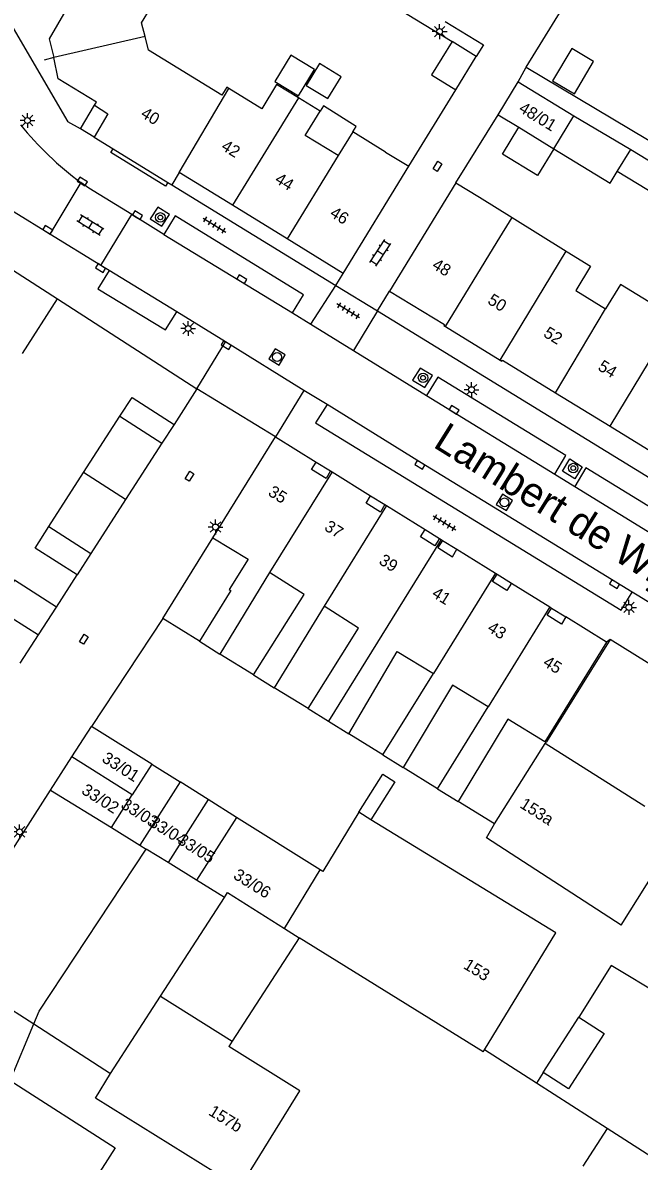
# Model space of a CAD drawing. Extents: x 132998 to 136004, y 396998 to 398512.
# Drawn here: x 133425.6 to 133477.5, y 397867.7 to 397963.6 of the extents above; entities that cross this region are included whole.
import ezdxf

# ---------------------------------------------------------------- set-up
doc = ezdxf.new("R2010")
doc.units = 0
for name, color, linetype in [('gg-afsc-erfafscheiding', 7, 'Continuous'), ('gg-afsc-hekwerk', 7, 'Continuous'), ('gg-afsc-muur', 7, 'Continuous'), ('gg-anno-huisnummerreeks BGT', 7, 'Continuous'), ('gg-anno-openbare ruimte label', 7, 'Continuous'), ('gg-bbg-bijgebouw', 7, 'Continuous'), ('gg-bbg-gedigitaliseerde bebouwing', 7, 'Continuous'), ('gg-bbg-gedigitaliseerde bijgebouw', 7, 'Continuous'), ('gg-bbg-hoofdgebouw', 7, 'Continuous'), ('gg-bbg-luifel en loopbrug', 7, 'Continuous'), ('gg-bbg-onder overbouw', 7, 'Continuous'), ('gg-bbg-pand overbouw', 7, 'Continuous'), ('gg-bbg-tussenscheiding', 7, 'Continuous'), ('gg-knt-verharding', 7, 'Continuous'), ('gg-knt-verharding nz', 7, 'Continuous'), ('gt-grn-vlakafsluiter', 7, 'Continuous'), ('gt-grn-weggrens', 7, 'Continuous'), ('gt-symb-boom', 7, 'Continuous'), ('gt-symb-klinker verharding', 7, 'Continuous'), ('gt-symb-kolk', 7, 'Continuous'), ('gt-symb-kolk center center', 7, 'Continuous'), ('gt-symb-lichtmast', 7, 'Continuous'), ('gt-symb-rioolschacht', 7, 'Continuous'), ('gt-symb-tegel verharding', 7, 'Continuous')]:
    doc.layers.add(name, color=color, linetype=linetype)

# ---------------------------------------------------------------- blocks, each defined once
blk = doc.blocks.new('gt0-BOOM')
at = {"layer": 'gt-symb-boom'}
for radius in [0.4, 0.2]:
    blk.add_circle((0, 0), radius, dxfattribs=at)
blk = doc.blocks.new('gt0-LMAST')
at = {"layer": 'gt-symb-lichtmast'}
for p, q in [((-0.182, 0.173), (-0.447, 0.438)), ((-0.005, 0.246), (-0.005, 0.621)), ((0.172, 0.173), (0.437, 0.438)), ((-0.255, -0.004), (-0.63, -0.004)), ((-0.182, -0.181), (-0.447, -0.446)), ((-0.005, -0.254), (-0.005, -0.629)), ((0.437, -0.446), (0.172, -0.181)), ((0.245, -0.004), (0.62, -0.004))]:
    blk.add_line(p, q, dxfattribs=at)
blk.add_circle((-0.005, -0.004), 0.25, dxfattribs=at)
blk = doc.blocks.new('gt0-KOLK')
at = {"layer": 'gt-symb-kolk'}
blk.add_lwpolyline([(0, 0), (0.375, 0), (0.375, 0.4), (-0.375, 0.4), (-0.375, 0), (0, 0)], dxfattribs=at)
blk = doc.blocks.new('gt0-KL1')
at = {"layer": 'gt-symb-klinker verharding'}
for p, q in [((-1.15, 0.3), (1.15, 0.3)), ((-1, -0.3), (-1, 0.3)), ((-0.5, 0.3), (-0.5, 0.45)), ((0, -0.3), (0, 0.3)), ((0.5, 0.3), (0.5, 0.45)), ((1, -0.3), (1, 0.3)), ((-1.15, -0.3), (1.15, -0.3)), ((-0.5, -0.45), (-0.5, -0.3)), ((0.5, -0.45), (0.5, -0.3))]:
    blk.add_line(p, q, dxfattribs=at)
blk = doc.blocks.new('gt0-KOLKCC')
at = {"layer": 'gt-symb-kolk center center'}
blk.add_lwpolyline([(-0.375, 0.2), (0.375, 0.2), (0.375, -0.2), (-0.375, -0.2)], close=True, dxfattribs=at)
blk = doc.blocks.new('gt0-TEG1')
at = {"layer": 'gt-symb-tegel verharding'}
for p, q in [((-1.125, 0), (1.125, 0)), ((-0.9, -0.25), (-0.9, 0.25)), ((-0.45, -0.25), (-0.45, 0.25)), ((0, -0.25), (0, 0.25)), ((0.45, -0.25), (0.45, 0.25)), ((0.9, -0.25), (0.9, 0.25))]:
    blk.add_line(p, q, dxfattribs=at)
blk = doc.blocks.new('gt0-RS')
at = {"layer": 'gt-symb-rioolschacht'}
blk.add_lwpolyline([(-0.5, -0.5), (0.5, -0.5), (0.5, 0.5), (-0.5, 0.5)], close=True, dxfattribs=at)
blk.add_circle((0, 0), 0.375, dxfattribs=at)

msp = doc.modelspace()

# ---------------------------------------------------------------- linework, layer by layer
at = {"layer": 'gg-afsc-erfafscheiding'}
for p, q in [((133467.987, 397959.829), (133500.702, 397940.273)), ((133428.55, 397940.32), (133440.28, 397932.74)), ((133440.28, 397932.74), (133438.36, 397929.75)), ((133440.488, 397911.502), (133437.42, 397913.411)), ((133445.051, 397908.68), (133442.219, 397910.419)), ((133449.642, 397905.845), (133446.781, 397907.593)), ((133455.916, 397901.956), (133453.07, 397903.712)), ((133460.544, 397899.077), (133457.653, 397900.884)), ((133465.32, 397896.147), (133462.284, 397898.01)), ((133469.426, 397875.2), (133468.863, 397874.313))]:
    msp.add_line(p, q, dxfattribs=at)
for points in [[(133452.519, 397966.43), (133452.815, 397965.486), (133453.519, 397964.851), (133455.624, 397965.741), (133461.761, 397961.967)], [(133461.167, 397963.674), (133464.396, 397961.689), (133463.797, 397960.715)], [(133483.745, 397879.058), (133475.138, 397884.2), (133472.427, 397879.856)]]:
    msp.add_lwpolyline(points, dxfattribs=at)
at = {"layer": 'gg-afsc-hekwerk'}
msp.add_line((133437.42, 397913.411), (133431.4, 397904.34), dxfattribs=at)
at = {"layer": 'gg-afsc-muur'}
for p, q in [((133467.987, 397959.829), (133474.941, 397971.075)), ((133428.249, 397960.622), (133427.42, 397960.42)), ((133458.121, 397951.479), (133462.073, 397957.913)), ((133462.083, 397950.072), (133465.643, 397955.82)), ((133437.42, 397913.411), (133441.63, 397920.204)), ((133468.863, 397874.313), (133464.486, 397877.129)), ((133474.802, 397870.492), (133468.863, 397874.313))]:
    msp.add_line(p, q, dxfattribs=at)
at = {"layer": 'gg-bbg-bijgebouw'}
for p, q in [((133463.797, 397960.715), (133461.761, 397961.967)), ((133462.073, 397957.913), (133463.797, 397960.715)), ((133465.643, 397955.82), (133467.331, 397958.581)), ((133467.331, 397958.581), (133472.01, 397955.72)), ((133430.74, 397925.7), (133433.802, 397930.439)), ((133438.36, 397929.75), (133437.337, 397928.167)), ((133437.337, 397928.167), (133434.27, 397923.42)), ((133431.35, 397918.88), (133430.2, 397917.08)), ((133443.123, 397915.772), (133440.488, 397911.502)), ((133425.414, 397909.658), (133426.953, 397912.043)), ((133440.488, 397911.502), (133442.219, 397910.419)), ((133479.219, 397909.058), (133475.06, 397911.65)), ((133445.051, 397908.68), (133446.781, 397907.593)), ((133449.642, 397905.845), (133451.356, 397904.779)), ((133429.759, 397901.779), (133431.4, 397904.34)), ((133436.477, 397901.157), (133431.4, 397904.34)), ((133451.356, 397904.779), (133453.07, 397903.712)), ((133427.964, 397898.977), (133429.759, 397901.779)), ((133455.916, 397901.956), (133457.653, 397900.884)), ((133436.477, 397901.157), (133438.859, 397899.665)), ((133441.24, 397898.171), (133438.859, 397899.665)), ((133418.624, 397884.4), (133427.964, 397898.977)), ((133460.544, 397899.077), (133462.284, 397898.01)), ((133443.621, 397896.679), (133441.24, 397898.171)), ((133450.653, 397892.271), (133443.621, 397896.679)), ((133469.426, 397875.2), (133472.427, 397879.856))]:
    msp.add_line(p, q, dxfattribs=at)
for points in [[(133433.802, 397930.439), (133434.83, 397932.03), (133438.36, 397929.75)], [(133430.2, 397917.08), (133426.66, 397919.35), (133427.815, 397921.151)]]:
    msp.add_lwpolyline(points, dxfattribs=at)
at = {"layer": 'gg-bbg-gedigitaliseerde bebouwing'}
for p, q in [((133450.65, 397956.124), (133448.833, 397957.236)), ((133453.391, 397954.373), (133452.171, 397952.379)), ((133456.161, 397952.678), (133453.391, 397954.373)), ((133456.161, 397952.678), (133458.121, 397951.479)), ((133462.083, 397950.072), (133464.059, 397948.876)), ((133464.059, 397948.876), (133466.805, 397947.165)), ((133466.805, 397947.165), (133471.356, 397944.328)), ((133471.356, 397944.328), (133471.438, 397944.277)), ((133425.595, 397935.713), (133428.55, 397940.32)), ((133446.38, 397917.288), (133442.219, 397910.419)), ((133451, 397914.451), (133446.781, 397907.593)), ((133455.916, 397901.956), (133460.204, 397908.799)), ((133460.544, 397899.077), (133464.79, 397905.984)), ((133466.438, 397904.957), (133462.284, 397898.01)), ((133465.32, 397896.147), (133469.598, 397902.889)), ((133476, 397887.596), (133479.483, 397893.191)), ((133464.382, 397876.959), (133448.881, 397886.549)), ((133474.802, 397870.492), (133472.776, 397867.333))]:
    msp.add_line(p, q, dxfattribs=at)
for points in [[(133435.924, 397962.401), (133435.629, 397963.564), (133439.403, 397969.757), (133440.113, 397969.324), (133440.217, 397969.495)], [(133442.966, 397958.029), (133442.79, 397958.138), (133442.365, 397957.449), (133436.217, 397961.242), (133435.924, 397962.401)], [(133448.833, 397957.236), (133446.991, 397958.364), (133445.732, 397956.323), (133442.966, 397958.029)], [(133452.171, 397952.379), (133449.397, 397954.077), (133450.65, 397956.124)], [(133471.438, 397944.277), (133473.42, 397943.063), (133472.169, 397941.021), (133474.684, 397939.48)], [(133480.551, 397938.694), (133475.939, 397941.523), (133474.684, 397939.48)], [(133445.051, 397908.68), (133449.31, 397915.446), (133446.38, 397917.288)], [(133449.642, 397905.845), (133453.895, 397912.616), (133451, 397914.451)], [(133474.768, 397911.424), (133469.569, 397903.049), (133466.438, 397904.957)], [(133453.07, 397903.712), (133457.131, 397910.628), (133460.204, 397908.799)], [(133464.79, 397905.984), (133461.788, 397907.798), (133457.653, 397900.884)]]:
    msp.add_lwpolyline(points, dxfattribs=at)
at = {"layer": 'gg-bbg-gedigitaliseerde bijgebouw'}
for p, q in [((133465.643, 397955.82), (133467.374, 397954.762)), ((133470.326, 397952.958), (133472.01, 397955.72)), ((133467.374, 397954.762), (133470.326, 397952.958)), ((133475.661, 397951.026), (133476.799, 397952.876)), ((133476.799, 397952.876), (133480.205, 397950.804)), ((133479.065, 397948.955), (133475.661, 397951.026)), ((133427.815, 397921.151), (133430.74, 397925.7)), ((133434.27, 397923.42), (133431.35, 397918.88)), ((133423.399, 397914.283), (133426.953, 397912.043)), ((133475.06, 397911.65), (133469.693, 397903.041)), ((133469.598, 397902.889), (133469.693, 397903.041)), ((133448.881, 397886.549), (133443.249, 397877.834)), ((133424.566, 397874.537), (133426.547, 397879.306)), ((133426.547, 397879.306), (133433.017, 397875.125)), ((133443.249, 397877.834), (133442.959, 397877.385))]:
    msp.add_line(p, q, dxfattribs=at)
for points in [[(133461.761, 397961.967), (133460.038, 397959.165), (133462.073, 397957.913)], [(133446.843, 397958.623), (133448.823, 397957.411), (133450.175, 397959.61), (133448.196, 397960.826), (133446.843, 397958.623)], [(133470.217, 397958.673), (133472.05, 397957.576), (133473.671, 397960.287), (133471.837, 397961.383), (133470.217, 397958.673)], [(133452.419, 397959.002), (133450.604, 397960.117), (133449.479, 397958.286), (133451.293, 397957.171), (133452.419, 397959.002)], [(133472.427, 397879.856), (133474.551, 397878.487), (133471.55, 397873.831), (133469.426, 397875.2)], [(133443.88, 397865.51), (133448.946, 397873.664), (133442.959, 397877.385)], [(133424.566, 397874.537), (133433.414, 397868.868), (133430.126, 397863.737)], [(133441.841, 397866.777), (133431.733, 397873.058), (133433.017, 397875.125)]]:
    msp.add_lwpolyline(points, dxfattribs=at)
at = {"layer": 'gg-bbg-hoofdgebouw'}
for p, q in [((133431.623, 397953.934), (133433.242, 397952.941)), ((133433.242, 397952.941), (133437.838, 397950.124)), ((133452.595, 397942.463), (133458.121, 397951.479)), ((133438.8, 397950.94), (133438.17, 397949.92)), ((133443.274, 397948.191), (133438.8, 397950.94)), ((133437.838, 397950.124), (133438.17, 397949.92)), ((133462.083, 397950.072), (133456.486, 397940.96)), ((133447.883, 397945.358), (133443.274, 397948.191)), ((133420.51, 397945.49), (133428.55, 397940.32)), ((133452.595, 397942.463), (133447.883, 397945.358)), ((133461.209, 397937.999), (133465.801, 397935.158)), ((133470.47, 397932.42), (133475.072, 397929.595)), ((133475.072, 397929.595), (133479.674, 397926.769)), ((133441.63, 397920.204), (133446.904, 397928.7)), ((133446.904, 397928.7), (133450.309, 397926.57)), ((133451.527, 397925.857), (133451.664, 397925.771)), ((133451.664, 397925.771), (133454.898, 397923.731)), ((133456.106, 397923), (133456.237, 397922.918)), ((133456.237, 397922.918), (133459.483, 397920.904)), ((133460.693, 397920.155), (133460.826, 397920.07)), ((133460.826, 397920.07), (133460.945, 397919.994)), ((133462.166, 397919.242), (133465.415, 397917.22)), ((133465.415, 397917.22), (133465.547, 397917.138)), ((133466.765, 397916.386), (133469.988, 397914.386)), ((133469.988, 397914.386), (133470.131, 397914.297)), ((133474.768, 397911.424), (133471.345, 397913.548)), ((133454.916, 397896.486), (133453.902, 397897.107)), ((133470.483, 397886.958), (133454.916, 397896.486)), ((133464.653, 397894.957), (133465.32, 397896.147)), ((133476, 397887.596), (133464.653, 397894.957)), ((133464.486, 397877.129), (133470.483, 397886.958)), ((133464.382, 397876.959), (133464.486, 397877.129)), ((133485.6, 397863.57), (133474.802, 397870.492))]:
    msp.add_line(p, q, dxfattribs=at)
for points in [[(133429.495, 397965.68), (133429.765, 397965.509), (133427.832, 397962.201), (133428.249, 397960.622)], [(133431.673, 397956.607), (133431.836, 397956.871), (133428.614, 397958.844), (133428.249, 397960.622)], [(133456.486, 397940.96), (133461.119, 397938.173), (133461.066, 397938.088), (133461.209, 397937.999)], [(133465.801, 397935.158), (133465.938, 397935.073), (133465.996, 397935.167), (133470.47, 397932.42)], [(133441.63, 397920.204), (133444.586, 397918.402), (133443.003, 397915.849), (133443.123, 397915.772)], [(133453.902, 397897.107), (133450.873, 397892.133), (133450.653, 397892.271)]]:
    msp.add_lwpolyline(points, dxfattribs=at)
at = {"layer": 'gg-bbg-luifel en loopbrug'}
for p, q in [((133472.01, 397955.72), (133476.799, 397952.876)), ((133426.953, 397912.043), (133428.451, 397914.363))]:
    msp.add_line(p, q, dxfattribs=at)
for points in [[(133453.391, 397954.373), (133453.673, 397954.815), (133450.932, 397956.566), (133450.65, 397956.124)], [(133470.326, 397952.958), (133468.95, 397950.7), (133465.998, 397952.503), (133467.374, 397954.762)], [(133470.326, 397952.958), (133475.067, 397950.06), (133475.661, 397951.026)], [(133428.451, 397914.363), (133424.92, 397916.635), (133423.399, 397914.283)], [(133453.902, 397897.107), (133455.923, 397900.315), (133456.929, 397899.681), (133454.916, 397896.486)]]:
    msp.add_lwpolyline(points, dxfattribs=at)
at = {"layer": 'gg-bbg-onder overbouw'}
for points in [[(133431.673, 397956.607), (133432.794, 397955.905), (133431.623, 397953.934)], [(133451.527, 397925.857), (133451.156, 397925.191), (133449.927, 397925.96), (133450.309, 397926.57)], [(133456.106, 397923), (133455.728, 397922.362), (133454.516, 397923.121), (133454.898, 397923.731)], [(133460.693, 397920.155), (133460.313, 397919.535), (133459.101, 397920.294), (133459.483, 397920.904)], [(133460.945, 397919.994), (133460.563, 397919.384), (133461.784, 397918.62), (133462.166, 397919.242)], [(133466.765, 397916.386), (133466.369, 397915.775), (133465.165, 397916.528), (133465.547, 397917.138)], [(133471.345, 397913.548), (133470.961, 397912.928), (133469.749, 397913.687), (133470.131, 397914.297)]]:
    msp.add_lwpolyline(points, dxfattribs=at)
at = {"layer": 'gg-bbg-pand overbouw'}
for p, q in [((133430.47, 397954.635), (133431.673, 397956.607)), ((133431.623, 397953.934), (133430.47, 397954.635)), ((133450.309, 397926.57), (133451.527, 397925.857)), ((133454.898, 397923.731), (133456.106, 397923)), ((133459.483, 397920.904), (133460.693, 397920.155)), ((133460.945, 397919.994), (133462.166, 397919.242)), ((133465.547, 397917.138), (133466.765, 397916.386)), ((133470.131, 397914.297), (133471.345, 397913.548))]:
    msp.add_line(p, q, dxfattribs=at)
at = {"layer": 'gg-bbg-tussenscheiding'}
for p, q in [((133435.924, 397962.401), (133428.249, 397960.622)), ((133438.8, 397950.94), (133442.966, 397958.029)), ((133448.833, 397957.236), (133443.274, 397948.191)), ((133452.171, 397952.379), (133447.883, 397945.358)), ((133465.543, 397945.11), (133466.805, 397947.165)), ((133461.209, 397937.999), (133465.543, 397945.11)), ((133465.801, 397935.158), (133471.356, 397944.328)), ((133470.47, 397932.42), (133474.684, 397939.48)), ((133475.072, 397929.595), (133480.551, 397938.694)), ((133433.802, 397930.439), (133437.337, 397928.167)), ((133434.27, 397923.42), (133430.74, 397925.7)), ((133451.664, 397925.771), (133446.38, 397917.288)), ((133456.237, 397922.918), (133451, 397914.451)), ((133427.815, 397921.151), (133431.35, 397918.88)), ((133460.826, 397920.07), (133451.356, 397904.779)), ((133465.415, 397917.22), (133460.204, 397908.799)), ((133469.988, 397914.386), (133464.79, 397905.984)), ((133475.232, 397899.33), (133469.598, 397902.889)), ((133434.843, 397898.591), (133429.759, 397901.779)), ((133436.477, 397901.157), (133434.843, 397898.591)), ((133438.859, 397899.665), (133435.471, 397894.347)), ((133427.964, 397898.977), (133433.08, 397895.822)), ((133433.08, 397895.822), (133434.843, 397898.591)), ((133477.972, 397897.6), (133475.232, 397899.33)), ((133441.24, 397898.171), (133437.863, 397892.872)), ((133443.621, 397896.679), (133440.256, 397891.396)), ((133433.08, 397895.822), (133435.471, 397894.347)), ((133435.471, 397894.347), (133436.021, 397894.008)), ((133437.863, 397892.872), (133436.021, 397894.008)), ((133440.256, 397891.396), (133437.863, 397892.872)), ((133447.653, 397887.325), (133450.653, 397892.271)), ((133442.608, 397889.946), (133440.256, 397891.396)), ((133437.216, 397881.627), (133442.608, 397889.946)), ((133447.653, 397887.325), (133448.881, 397886.549)), ((133418.624, 397884.4), (133426.547, 397879.306)), ((133433.017, 397875.125), (133437.216, 397881.627)), ((133437.216, 397881.627), (133443.249, 397877.834))]:
    msp.add_line(p, q, dxfattribs=at)
for points in [[(133426.547, 397879.306), (133426.993, 397880.38), (133436.021, 397894.008)], [(133442.608, 397889.946), (133442.869, 397890.348), (133447.653, 397887.325)]]:
    msp.add_lwpolyline(points, dxfattribs=at)
at = {"layer": 'gg-knt-verharding'}
for p, q in [((133467.331, 397958.581), (133467.987, 397959.829)), ((133430.47, 397954.635), (133429.43, 397955.224)), ((133430.524, 397950.105), (133427.891, 397945.771)), ((133438.17, 397949.92), (133451.973, 397941.449)), ((133432.205, 397943.118), (133434.791, 397947.412)), ((133437.495, 397945.748), (133434.791, 397947.412)), ((133432.205, 397943.118), (133427.891, 397945.771)), ((133432.884, 397942.7), (133432.205, 397943.118)), ((133451.973, 397941.449), (133455.469, 397939.303)), ((133442.689, 397936.689), (133438.58, 397939.224)), ((133448.32, 397939.137), (133449.865, 397938.186)), ((133455.469, 397939.303), (133492.602, 397916.529)), ((133449.865, 397938.186), (133453.451, 397935.979)), ((133449.292, 397932.616), (133442.689, 397936.689)), ((133453.451, 397935.979), (133459.614, 397932.186)), ((133446.904, 397928.7), (133440.28, 397932.74)), ((133451.234, 397931.418), (133449.292, 397932.616)), ((133470.393, 397925.566), (133472.085, 397924.537)), ((133428.451, 397914.363), (133430.2, 397917.08)), ((133477.348, 397915.373), (133476.916, 397915.64)), ((133481.528, 397912.794), (133477.348, 397915.373))]:
    msp.add_line(p, q, dxfattribs=at)
for points in [[(133425.012, 397972.007), (133422.23, 397967.494), (133429.43, 397955.224)], [(133427.891, 397945.771), (133421.863, 397949.479), (133418.418, 397952.027), (133415.953, 397954.728), (133414.974, 397954.257)], [(133437.838, 397950.124), (133437.644, 397949.808), (133433.049, 397952.626), (133433.242, 397952.941)], [(133434.791, 397947.412), (133431.173, 397949.64), (133430.524, 397950.105)], [(133436.337, 397947.054), (133437.342, 397946.43), (133437.982, 397947.42), (133436.978, 397948.044), (133436.337, 397947.054)], [(133448.32, 397939.137), (133449.246, 397940.66), (133438.462, 397947.314), (133437.495, 397945.748)], [(133432.884, 397942.7), (133431.944, 397941.151), (133437.628, 397937.712), (133438.58, 397939.224)], [(133458.434, 397933.472), (133459.463, 397932.855), (133460.096, 397933.876), (133459.067, 397934.493), (133458.434, 397933.472)], [(133470.393, 397925.566), (133471.339, 397927.129), (133460.566, 397933.728), (133459.614, 397932.186)], [(133451.234, 397931.418), (133450.259, 397929.893), (133475.993, 397914.116), (133476.916, 397915.64)], [(133471.049, 397925.824), (133471.663, 397926.849), (133472.707, 397926.187), (133472.093, 397925.162), (133471.049, 397925.824)], [(133481.964, 397918.458), (133482.94, 397920.014), (133473.006, 397926.106), (133472.085, 397924.537)]]:
    msp.add_lwpolyline(points, dxfattribs=at)
msp.add_arc((133447.124, 397972.581), 27.942, 219.07114, 233.55211, dxfattribs=at)
at = {"layer": 'gg-knt-verharding nz'}
for p, q in [((133437.495, 397945.748), (133448.32, 397939.137)), ((133438.58, 397939.224), (133432.884, 397942.7)), ((133459.614, 397932.186), (133470.393, 397925.566)), ((133472.085, 397924.537), (133481.964, 397918.458))]:
    msp.add_line(p, q, dxfattribs=at)
msp.add_lwpolyline([(133476.916, 397915.64), (133459.151, 397926.522), (133451.234, 397931.418)], dxfattribs=at)
at = {"layer": 'gt-grn-vlakafsluiter'}
msp.add_line((133475.06, 397911.65), (133474.768, 397911.424), dxfattribs=at)
at = {"layer": 'gt-grn-weggrens'}
for p, q in [((133451.973, 397941.449), (133452.595, 397942.463)), ((133449.865, 397938.186), (133451.973, 397941.449)), ((133455.469, 397939.303), (133456.486, 397940.96)), ((133455.469, 397939.303), (133453.451, 397935.979)), ((133440.28, 397932.74), (133442.689, 397936.689)), ((133449.292, 397932.616), (133446.904, 397928.7))]:
    msp.add_line(p, q, dxfattribs=at)

# ---------------------------------------------------------------- block references
at = {"layer": 'gt-symb-boom'}
for p in [(133437.203, 397947.175), (133459.315, 397933.677), (133471.956, 397926.079)]:
    msp.add_blockref('gt0-BOOM', p, dxfattribs=at)
at = {"layer": 'gt-symb-klinker verharding'}
for p, rotation in [((133431.313, 397946.524), 148.24980309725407), ((133455.717, 397944.185), 56.99293824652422)]:
    msp.add_blockref('gt0-KL1', p, dxfattribs=dict(at, rotation=rotation))
at = {"layer": 'gt-symb-kolk'}
for p, rotation in [((133430.533, 397950.032), -32.08436154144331), ((133435.174, 397947.191), -31.46487302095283), ((133427.62, 397945.957), -31.671318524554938), ((133432.276, 397943.083), 147.78810263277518), ((133443.955, 397941.803), -31.417706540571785), ((133442.85, 397936.591), 148.5351269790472), ((133461.818, 397930.817), -31.798912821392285), ((133459.151, 397926.522), 148.48628372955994), ((133475.536, 397916.478), 148.74151468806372)]:
    msp.add_blockref('gt0-KOLK', p, dxfattribs=dict(at, rotation=rotation))
at = {"layer": 'gt-symb-kolk center center'}
for p, rotation in [((133460.523, 397951.473), -121.87781648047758), ((133439.663, 397925.389), 57.12021809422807), ((133430.758, 397911.67), 57.24756055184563)]:
    msp.add_blockref('gt0-KOLKCC', p, dxfattribs=dict(at, rotation=rotation))
at = {"layer": 'gt-symb-lichtmast'}
for p in [(133460.711, 397962.816), (133426.025, 397955.332), (133439.549, 397937.825), (133463.399, 397932.675), (133441.845, 397921.118), (133476.647, 397914.358), (133425.357, 397895.466)]:
    msp.add_blockref('gt0-LMAST', p, dxfattribs=at)
at = {"layer": 'gt-symb-rioolschacht'}
for p, rotation in [((133447.03, 397935.431), -31.46487302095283), ((133466.166, 397923.185), -31.59249156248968)]:
    msp.add_blockref('gt0-RS', p, dxfattribs=dict(at, rotation=rotation))
at = {"layer": 'gt-symb-tegel verharding'}
for p, rotation in [((133441.762, 397946.532), -31.671318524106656), ((133453.011, 397939.31), 148.4563265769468), ((133461.12, 397921.478), -31.513716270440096)]:
    msp.add_blockref('gt0-TEG1', p, dxfattribs=dict(at, rotation=rotation))

# ---------------------------------------------------------------- texts
at = {"layer": 'gg-anno-huisnummerreeks BGT'}
for s, rotation, p in [('40', 328.5, (133435.474, 397955.679)), ('48/01', 328.6, (133467.294, 397956.12)), ('42', 328.4, (133442.251, 397952.928)), ('44', 328.4, (133446.765, 397950.154)), ('46', 328.5, (133451.393, 397947.308)), ('48', 329, (133459.997, 397942.931)), ('50', 328.2, (133464.672, 397939.973)), ('52', 328.5, (133469.376, 397937.198)), ('54', 328.5, (133473.955, 397934.387)), ('35', 328, (133446.2, 397923.832)), ('37', 327.7, (133450.931, 397920.913)), ('39', 328.2, (133455.524, 397918.064)), ('41', 328.1, (133459.98, 397915.302)), ('43', 328.2, (133464.655, 397912.399)), ('45', 328.2, (133469.333, 397909.5)), ('33/01', 327.3, (133432.206, 397901.424)), ('33/02', 327.4, (133430.487, 397898.741)), ('33/03', 327.9, (133433.799, 397897.526)), ('153a', 327.6, (133467.383, 397897.559)), ('33/04', 327.9, (133436.176, 397896.035)), ('33/05', 327.9, (133438.56, 397894.54)), ('33/06', 327.9, (133443.266, 397891.591)), ('153', 328.6, (133462.638, 397884.017)), ('157b', 328.1, (133441.183, 397871.692))]:
    msp.add_text(s, height=1, rotation=rotation, dxfattribs=at).set_placement(p)
at = {"layer": 'gg-anno-openbare ruimte label'}
msp.add_text('Lambert de Wijsstraat', height=2.5, rotation=328, dxfattribs=at).set_placement((133460.066, 397927.906))

doc.saveas('drawing.dxf')
